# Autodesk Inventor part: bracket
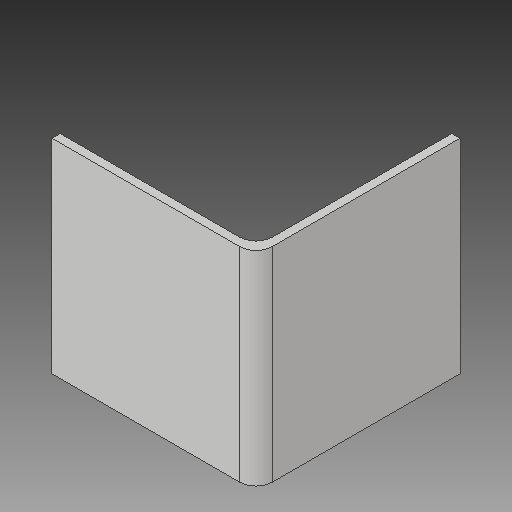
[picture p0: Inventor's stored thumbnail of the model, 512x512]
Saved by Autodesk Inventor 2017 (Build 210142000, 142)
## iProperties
Created: 2020-03
Part Number: bracket
Material: Generic
Document SubType Name: Modeling
Designer: user
Density: 1 g/cm^3
Appearance: Default
Author: user
Revision Number: ANY
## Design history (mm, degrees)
fillet "Fillet1"
body "Solid1"
